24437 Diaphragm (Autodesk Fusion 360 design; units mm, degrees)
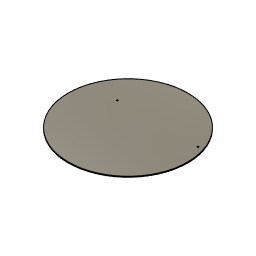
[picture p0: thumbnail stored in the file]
sketch "Main Profile" plane through (0, 0, 0) normal (0, 0, 1) x axis (1, 0, 0)
  line L1 (36.5125, 0) -> (0, 0)
  line L2 (0, 11.1125) -> (0, 0)
  line L3 (34.7804, 11.1125) -> (0, 11.1125)
  line L4 (-17.6071, 11.1125) -> (0, 11.1125)
  circle C1 centre (0, 0) radius 36.5125
  circle C2 centre (31.6054, 11.1125) radius 0.3969
  circle C3 centre (-17.6071, 11.1125) radius 0.3969
  point P1 (0, 0)
  point P2 (0, 0)
  point P3 (0, 0)
  point P4 (36.5125, 0)
  point P5 (0, 0)
  point P7 (34.7804, 11.1125)
  point P8 (31.6054, 11.1125)
  point P9 (-17.6071, 11.1125)
  point P10 (-17.6071, 11.1125)
  point P6 (0, 11.1125)
  coincident P1 P2
  coincident P1 P3
  coincident C1 P4
  horizontal L1
  coincident P2 P5
  perpendicular L1 L2
  perpendicular L2 L3
  coincident C1 P7
  coincident L3 P8
  perpendicular L2 L4
  coincident P9 P10
  dimension "d1" diameter C1 = 73.025 (= "2 7/8")
  dimension "d4" distance P5 P6 = 11.1125 (= "( 7 / 16 ) * 1 in")
  dimension "d5" distance P7 P8 = 3.175 (= "( 1 / 8 ) * 1 in")
  dimension "d6" distance P8 P9 = 49.2125 (= "1 15/16")
  dimension "d7" diameter C2 = 0.7937 (= "( 1 / 32 ) * 1 in")
  dimension "d8" diameter C3 = 0.7937 (= "( 1 / 32 ) * 1 in")
extrude "Extrude1" new body sketch "Main Profile" profile of C1 C2 C3 along normal blind 0.508 bodies "24437 Diaphragm"
named bodies: "24437 Diaphragm"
